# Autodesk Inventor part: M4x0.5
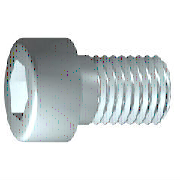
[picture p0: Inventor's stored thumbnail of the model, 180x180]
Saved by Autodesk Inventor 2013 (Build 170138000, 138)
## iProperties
IsCustomPart: 1
Company: 한국ATC센터
Created: 2014-11
Part Number: M4x0.5
Material: Steel, Mild
Description: 6각머리 태핑 나사
Document SubType Name: Modeling
Standard: KS B 1003
Designer: KYOUNG IL JANG
Standards Organization: KS
Language: ko-KR
Size Designation: M 4 x 16
Categories: <MemberInstance><Categories><Category DisplayName="조임쇠" InternalName="e4da775c-781d-43d5-af7c-5136215cf5a6" Mnemonic="FSTN"><Category DisplayName="볼트" InternalN
Density: 7.86 g/cm^3
Mass: 2.62973 g
Surface Area: 3.81119 cm^2
Volume: 0.334572 cm^3
Author: KYOUNG IL JANG
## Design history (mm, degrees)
revolve "본체" stored, may be unused: angle "d10" = 90 deg
sketch "스케치2"
  geometry: L1 (0, -4.9)-(0, 4.9) reference; L2 (-4.9, 0)-(4.9, 0) reference; L3 (1.732, 0)-(0.866, -1.5); L4 (0.866, -1.5)-(-0.866, -1.5); L5 (-0.866, -1.5)-(-1.732, 0); L6 (-1.732, 0)-(-0.866, 1.5); L7 (-0.866, 1.5)-(0.866, 1.5); L8 (0.866, 1.5)-(1.732, 0); 2 further points
  constraints: 12 end point, 1 coincident, 1 horizontal alignment, 1 point on line, 12 other
extrude "슬롯" join sketch "스케치2" stored distance "d11" = 10; taper "d12" = 0 deg
workplane "Work Plane1"
fillet "Fillet2" dims "d30" = 0.1 (= R)
body "Solid1"
fillet "모깎기1" dims "d17" = 0.4 (= RR)
feature "스레드" dims "d13" = 14.25 (= GEL), "d14" = 0
chamfer "모따기1" distance "d15" = 0.42941 (= -0.5 x SPD + 0.5 x GD); stored, may be unused: second distance "d16" = 0.42941 (= GUL), angle "d27" = 45 deg
sketch "스케치1"
  geometry: L1 (-1, 0)-(16, 0); L2 (16, 0)-(16, 2); L3 (16, 2)-(1.75, 2); L4 (1.75, 2)-(1.32, 2); L5 (1.32, 2)-(0, 2); L6 (0, 2)-(0, 3.5); L7 (0, 3.5)-(-4, 3.5); L8 (-4, 3.5)-(-4, 1.732); L9 (-4, 1.732)-(-2, 1.732); L10 (-2, 1.732)-(-1, 0); L11 (-8, 0)-(20, 0) reference; L12 (0, -0.7)-(0, 4.2) reference; L13 (1.75, 2)-(0, 2)
  constraints: 22 end point, 6 parallel, 2 collinear, 2 perpendicular, 1 horizontal, 1 point on line
  dimensions: "d1" = 14.25 distance from line of L3.end L2 (= GEL); "d2" = 0.42952 distance of L4.end L3.end (computed from GAL); "d3" = 4 distance between parallel lines of L8 L6 (= KOH); "d4" = 2 distance of L8.end L9.end (= INTI); "d5" = 60 deg angle of L10 L1; "d6" = 4 diameter of L3 L1 (= GD); "d7" = 4 diameter of L5 L1 (= BDM); "d8" = 3.4641 diameter of L9 L1 (= 1.1547 x SW); "d9" = 7 diameter of L7 L1 (= KOD); "d26" = 16 distance between parallel lines of L12 L2 (= NLG)
other parameters: "GD" = 4 (= NND) [user parameter; used in 2 equation terms], "NLG" = 16 [user parameter; used in 1 equation term], "GEL" = 14.25 [user parameter; used in 2 equation terms], "KOD" = 7 [user parameter; used in 1 equation term], "KOH" = 4 [user parameter; used in 1 equation term], "INTI" = 2 [user parameter; used in 1 equation term], "GAL" = 0.42941 (= 0.61345 x PTC) [user parameter; used in 1 equation term], "GUL" = 0.42941 (= 0.61345 x PTC) [user parameter; used in 1 equation term], "BDM" = 4 (= NND) [user parameter; used in 1 equation term], "SW" = 3 [user parameter; used in 2 equation terms], "RR" = 0.4 [user parameter; used in 1 equation term], "SPD" = 3.14117 (= NND - 1.2269 x PTC) [user parameter; used in 1 equation term], "d19" = 0, "d28" = 0, "d29" = 0, "R" = 0.1 [user parameter; used in 1 equation term], "PHH" = 0.2 [user parameter], "GD1" = 3.14117 (= THREADDIA - 1.2269 x PTC) [user parameter], "THREADDIA" = 4 [user parameter; used in 1 equation term], "FAWI" = 45 deg [user parameter], "TPU" = 14.28571 (computed from PTC) [user parameter], "PTC" = 0.7 [user parameter; used in 5 equation terms], "NND" = 4 [user parameter; used in 3 equation terms], "TOA" = 30 deg [user parameter], "E0" = 3.465 (= 1.155 x SW) [user parameter]
